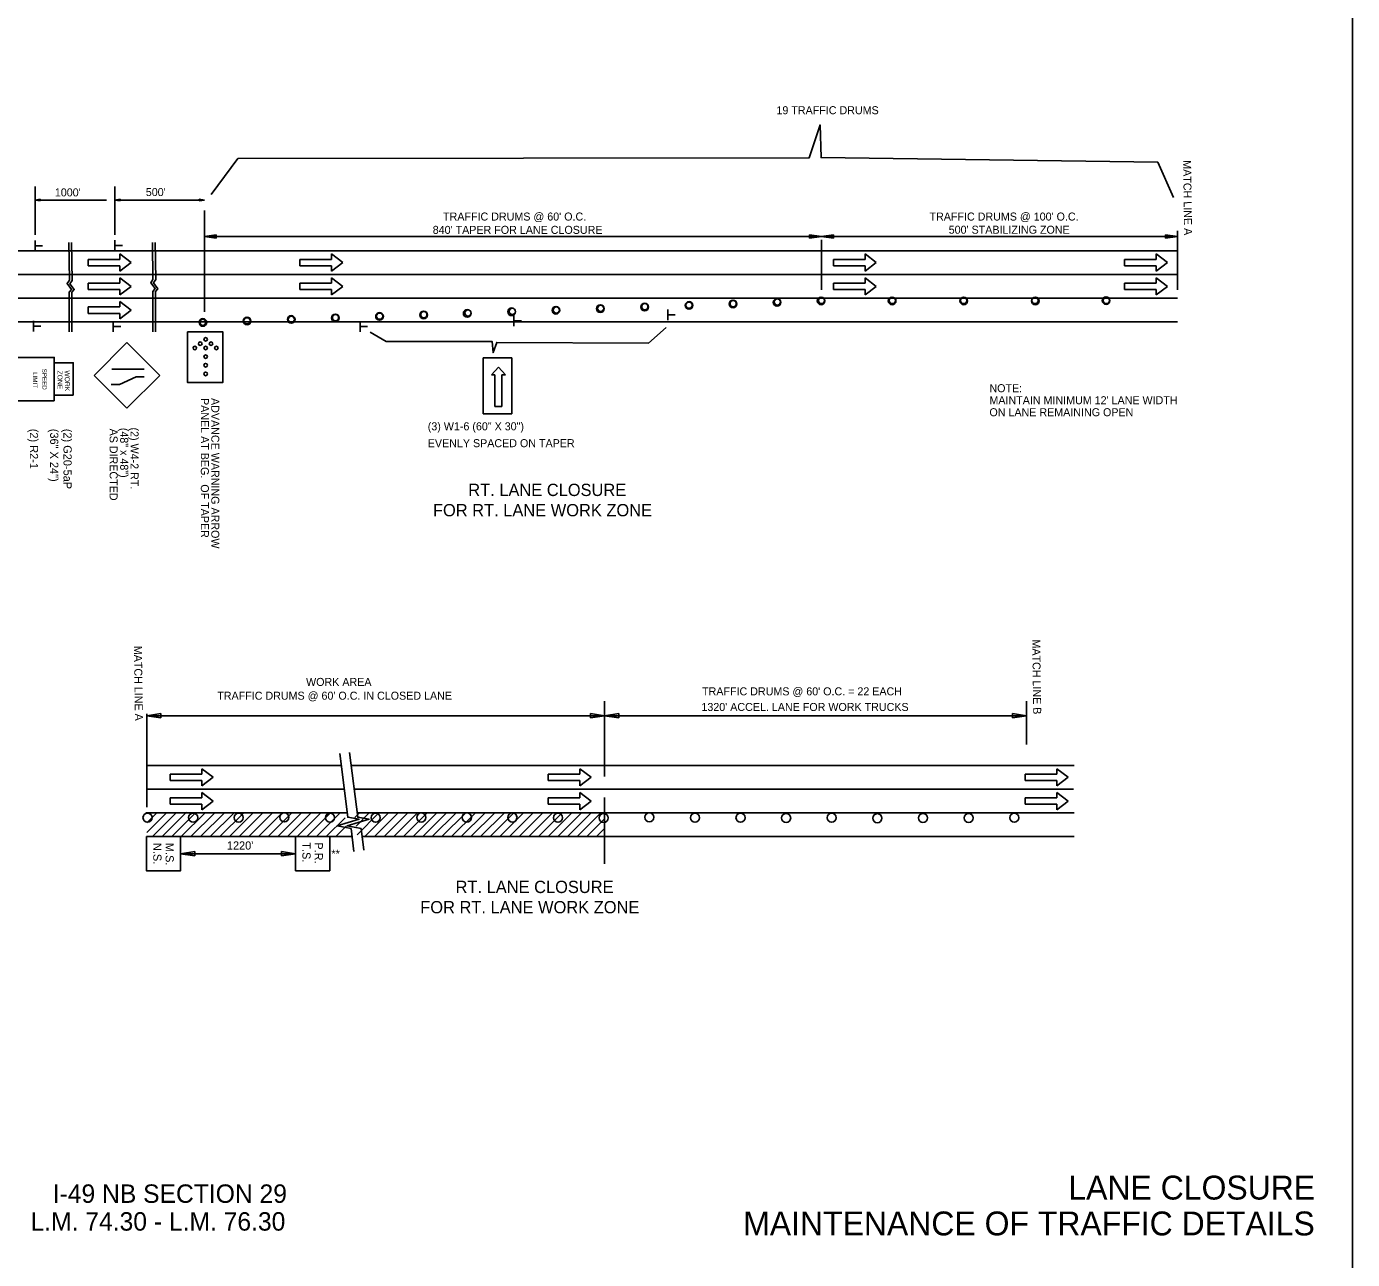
# Model space of a CAD drawing. Extents: x -100 to 745, y -1581 to -107.
# Drawn here: x 248.3 to 345.4, y -368.8 to -278.6 of the extents above; entities that cross this region are included whole.
import ezdxf

# ---------------------------------------------------------------- set-up
doc = ezdxf.new("R2010")
doc.units = 0
for name, color, linetype in [('Default', 7, 'Continuous'), ('R_Contour Annot', 7, 'Continuous'), ('R_Detour Annot', 7, 'Continuous'), ('R_Draft', 7, 'Continuous'), ('R_MOT', 7, 'Continuous'), ('R_ROW', 7, 'Continuous')]:
    doc.layers.add(name, color=color, linetype=linetype)

msp = doc.modelspace()

# ---------------------------------------------------------------- linework, layer by layer
at = {"layer": 'Default'}
for p, q in [((248.914, -290.299), (248.914, -293.82)), ((254.765, -290.299), (254.765, -293.82)), ((249.289, -291.222), (248.914, -291.278)), ((248.914, -291.278), (254.133, -291.278)), ((249.289, -291.335), (248.914, -291.278)), ((249.289, -291.232), (248.977, -291.278)), ((249.289, -291.325), (248.977, -291.278)), ((249.289, -291.241), (249.041, -291.278)), ((249.289, -291.316), (249.041, -291.278)), ((249.289, -291.25), (249.104, -291.278)), ((249.289, -291.306), (249.104, -291.278)), ((249.289, -291.26), (249.167, -291.278)), ((249.289, -291.297), (249.167, -291.278)), ((249.289, -291.27), (249.23, -291.278)), ((249.289, -291.287), (249.23, -291.278)), ((249.289, -291.335), (249.289, -291.222)), ((255.14, -291.222), (254.765, -291.278)), ((254.765, -291.278), (261.312, -291.278)), ((255.14, -291.335), (254.765, -291.278)), ((255.14, -291.232), (254.828, -291.278)), ((255.14, -291.325), (254.828, -291.278)), ((255.14, -291.241), (254.892, -291.278)), ((255.14, -291.316), (254.892, -291.278)), ((255.14, -291.25), (254.955, -291.278)), ((255.14, -291.306), (254.955, -291.278)), ((255.14, -291.26), (255.018, -291.278)), ((255.14, -291.297), (255.018, -291.278)), ((255.14, -291.27), (255.081, -291.278)), ((255.14, -291.287), (255.081, -291.278)), ((255.14, -291.335), (255.14, -291.222)), ((260.937, -291.222), (261.312, -291.278)), ((260.937, -291.222), (260.937, -291.335)), ((260.937, -291.232), (261.25, -291.278)), ((260.937, -291.241), (261.185, -291.278)), ((260.937, -291.25), (261.123, -291.278)), ((260.937, -291.26), (261.059, -291.278)), ((260.937, -291.27), (260.997, -291.278)), ((260.937, -291.335), (261.312, -291.278)), ((260.937, -291.297), (261.059, -291.278)), ((260.937, -291.316), (261.185, -291.278)), ((260.937, -291.325), (261.25, -291.278)), ((260.937, -291.306), (261.123, -291.278)), ((260.937, -291.287), (260.997, -291.278)), ((261.312, -292.038), (261.312, -299.452)), ((248.914, -295.015), (248.914, -294.233)), ((254.765, -294.994), (254.765, -294.212)), ((261.312, -293.95), (262.182, -293.82)), ((306.513, -293.95), (261.312, -293.95)), ((262.182, -294.08), (261.312, -293.95)), ((262.182, -293.82), (262.182, -294.08)), ((305.644, -294.08), (305.644, -293.82)), ((305.644, -293.82), (306.513, -293.95)), ((306.513, -293.95), (305.644, -294.08)), ((306.513, -293.95), (307.383, -293.82)), ((332.591, -293.95), (306.513, -293.95)), ((307.383, -294.08), (306.513, -293.95)), ((306.513, -294.184), (306.513, -297.841)), ((307.383, -293.82), (307.383, -294.08)), ((331.722, -294.08), (331.722, -293.82)), ((331.722, -293.82), (332.591, -293.95)), ((332.591, -293.95), (331.722, -294.08)), ((332.591, -293.536), (332.591, -297.841)), ((245.32, -294.99), (261.312, -294.99)), ((248.925, -294.626), (249.459, -294.626)), ((254.777, -294.605), (255.311, -294.605)), ((255.132, -295.227), (255.132, -295.622)), ((255.132, -295.227), (255.953, -295.859)), ((261.312, -294.32), (261.312, -297.841)), ((261.312, -294.99), (332.591, -294.99)), ((270.63, -295.227), (270.63, -295.622)), ((270.63, -295.227), (271.451, -295.859)), ((309.709, -295.227), (309.709, -295.622)), ((309.709, -295.227), (310.53, -295.859)), ((331.029, -295.227), (331.029, -295.622)), ((331.029, -295.227), (331.849, -295.859)), ((255.132, -295.622), (252.807, -295.622)), ((252.807, -295.622), (252.807, -296.097)), ((255.132, -296.097), (252.807, -296.097)), ((255.953, -295.859), (255.132, -296.492)), ((255.132, -296.097), (255.132, -296.492)), ((270.63, -295.622), (268.304, -295.622)), ((268.304, -295.622), (268.304, -296.097)), ((270.63, -296.097), (268.304, -296.097)), ((271.451, -295.859), (270.63, -296.492)), ((270.63, -296.097), (270.63, -296.492)), ((309.709, -295.622), (307.384, -295.622)), ((307.384, -295.622), (307.384, -296.097)), ((309.709, -296.097), (307.384, -296.097)), ((310.53, -295.859), (309.709, -296.492)), ((309.709, -296.097), (309.709, -296.492)), ((331.029, -295.622), (328.703, -295.622)), ((328.703, -295.622), (328.703, -296.097)), ((331.029, -296.097), (328.703, -296.097)), ((331.849, -295.859), (331.029, -296.492)), ((331.029, -296.097), (331.029, -296.492)), ((245.32, -296.729), (261.312, -296.729)), ((255.132, -296.966), (255.132, -297.361)), ((255.132, -296.966), (255.953, -297.598)), ((261.312, -296.729), (332.591, -296.729)), ((270.63, -296.966), (270.63, -297.361)), ((270.63, -296.966), (271.451, -297.598)), ((309.709, -296.966), (309.709, -297.361)), ((309.709, -296.966), (310.53, -297.598)), ((331.029, -296.966), (331.029, -297.361)), ((331.029, -296.966), (331.849, -297.598)), ((255.132, -297.361), (252.807, -297.361)), ((252.807, -297.361), (252.807, -297.835)), ((255.132, -297.835), (252.807, -297.835)), ((255.953, -297.598), (255.132, -298.23)), ((255.132, -297.835), (255.132, -298.23)), ((270.63, -297.361), (268.304, -297.361)), ((268.304, -297.361), (268.304, -297.835)), ((270.63, -297.835), (268.304, -297.835)), ((271.451, -297.598), (270.63, -298.23)), ((270.63, -297.835), (270.63, -298.23)), ((309.709, -297.361), (307.384, -297.361)), ((307.384, -297.361), (307.384, -297.835)), ((309.709, -297.835), (307.384, -297.835)), ((310.53, -297.598), (309.709, -298.23)), ((309.709, -297.835), (309.709, -298.23)), ((331.029, -297.361), (328.703, -297.361)), ((328.703, -297.361), (328.703, -297.835)), ((331.029, -297.835), (328.703, -297.835)), ((331.849, -297.598), (331.029, -298.23)), ((331.029, -297.835), (331.029, -298.23)), ((245.32, -298.467), (261.312, -298.467)), ((255.132, -299.099), (252.807, -299.099)), ((252.807, -299.099), (252.807, -299.574)), ((255.132, -298.704), (255.132, -299.099)), ((255.132, -298.704), (255.953, -299.336)), ((261.312, -298.467), (332.591, -298.467)), ((255.132, -299.574), (252.807, -299.574)), ((255.953, -299.336), (255.132, -299.969)), ((255.132, -299.574), (255.132, -299.969)), ((283.986, -300.501), (283.986, -299.719)), ((295.257, -300.075), (295.257, -299.293)), ((295.268, -299.686), (295.802, -299.686)), ((245.32, -300.206), (261.312, -300.206)), ((248.788, -300.903), (248.788, -300.12)), ((248.799, -300.514), (249.333, -300.514)), ((254.639, -300.924), (254.639, -300.141)), ((254.65, -300.535), (255.184, -300.535)), ((261.312, -300.206), (332.591, -300.206)), ((272.715, -300.928), (272.715, -300.146)), ((272.727, -300.539), (273.261, -300.539)), ((283.997, -300.112), (284.532, -300.112)), ((255.646, -301.709), (253.237, -304.119)), ((255.646, -301.709), (258.056, -304.119)), ((254.53, -303.655), (256.9, -303.655)), ((282.333, -304.076), (282.851, -303.507)), ((282.851, -303.507), (283.371, -304.076)), ((253.237, -304.119), (255.646, -306.528)), ((254.479, -304.779), (255.092, -304.779)), ((255.092, -304.779), (256.317, -304.217)), ((258.056, -304.119), (255.646, -306.528)), ((256.317, -304.217), (256.9, -304.217)), ((282.592, -304.076), (282.333, -304.076)), ((282.592, -306.406), (282.592, -304.076)), ((283.111, -306.406), (283.111, -304.076)), ((283.111, -304.076), (283.371, -304.076)), ((282.592, -306.406), (283.111, -306.406)), ((290.63, -327.957), (290.63, -333.492)), ((321.54, -327.957), (321.54, -331.149)), ((257.095, -329.036), (258.125, -328.881)), ((257.095, -328.889), (257.095, -333.992)), ((290.63, -329.036), (257.095, -329.036)), ((258.125, -329.19), (257.095, -329.036)), ((258.125, -328.881), (258.125, -329.19)), ((289.6, -329.19), (289.6, -328.882)), ((289.6, -328.882), (290.63, -329.036)), ((290.63, -329.036), (289.6, -329.19)), ((290.63, -329.036), (291.66, -328.881)), ((321.54, -329.036), (290.63, -329.036)), ((291.66, -329.19), (290.63, -329.036)), ((291.66, -328.881), (291.66, -329.19)), ((320.51, -329.19), (320.51, -328.881)), ((320.51, -328.881), (321.54, -329.036)), ((321.54, -329.036), (320.51, -329.19)), ((257.095, -329.695), (257.095, -335.73)), ((257.095, -330.627), (257.095, -335.73)), ((257.095, -330.627), (257.095, -335.73)), ((257.095, -332.673), (271.346, -332.673)), ((261.133, -332.91), (261.133, -333.305)), ((261.133, -332.91), (261.954, -333.543)), ((272.074, -332.673), (290.63, -332.673)), ((288.812, -332.91), (288.812, -333.305)), ((288.812, -332.91), (289.632, -333.543)), ((290.63, -332.673), (325.019, -332.673)), ((323.754, -332.91), (323.754, -333.305)), ((323.754, -332.91), (324.575, -333.543)), ((261.133, -333.305), (258.808, -333.305)), ((258.808, -333.305), (258.808, -333.78)), ((261.133, -333.78), (258.808, -333.78)), ((261.954, -333.543), (261.133, -334.175)), ((261.133, -333.78), (261.133, -334.175)), ((288.812, -333.305), (286.486, -333.305)), ((286.486, -333.305), (286.486, -333.78)), ((288.812, -333.78), (286.486, -333.78)), ((289.632, -333.543), (288.812, -334.175)), ((288.812, -333.78), (288.812, -334.175)), ((323.754, -333.305), (321.429, -333.305)), ((321.429, -333.305), (321.429, -333.78)), ((323.754, -333.78), (321.429, -333.78)), ((324.575, -333.543), (323.754, -334.175)), ((323.754, -333.78), (323.754, -334.175)), ((257.095, -334.411), (271.563, -334.411)), ((261.133, -335.044), (258.808, -335.044)), ((258.808, -335.044), (258.808, -335.518)), ((261.133, -334.649), (261.133, -335.044)), ((261.133, -334.649), (261.954, -335.281)), ((272.291, -334.411), (290.581, -334.411)), ((288.812, -335.044), (286.486, -335.044)), ((286.486, -335.044), (286.486, -335.518)), ((288.812, -334.649), (288.812, -335.044)), ((288.812, -334.649), (289.632, -335.281)), ((290.581, -334.411), (324.97, -334.411)), ((323.754, -335.044), (321.429, -335.044)), ((321.429, -335.044), (321.429, -335.518)), ((323.754, -334.649), (323.754, -335.044)), ((323.754, -334.649), (324.575, -335.281)), ((261.133, -335.518), (258.808, -335.518)), ((261.954, -335.281), (261.133, -335.913)), ((261.133, -335.518), (261.133, -335.913)), ((288.812, -335.518), (286.486, -335.518)), ((289.632, -335.281), (288.812, -335.913)), ((288.812, -335.518), (288.812, -335.913)), ((323.754, -335.518), (321.429, -335.518)), ((324.575, -335.281), (323.754, -335.913)), ((323.754, -335.518), (323.754, -335.913)), ((257.025, -336.15), (271.718, -336.15)), ((257.096, -337.589), (258.535, -336.15)), ((257.096, -336.882), (257.828, -336.15)), ((257.504, -337.888), (259.242, -336.15)), ((258.211, -337.888), (260.004, -336.094)), ((258.918, -337.888), (260.656, -336.15)), ((259.625, -337.888), (261.363, -336.15)), ((260.332, -337.888), (262.07, -336.15)), ((261.039, -337.888), (262.777, -336.15)), ((261.746, -337.888), (263.485, -336.15)), ((262.453, -337.888), (264.192, -336.15)), ((263.16, -337.888), (264.899, -336.15)), ((263.868, -337.888), (265.606, -336.15)), ((264.575, -337.888), (266.313, -336.15)), ((265.282, -337.888), (267.02, -336.15)), ((265.989, -337.888), (267.727, -336.15)), ((266.696, -337.888), (268.434, -336.15)), ((267.403, -337.888), (269.141, -336.15)), ((268.11, -337.888), (269.849, -336.15)), ((268.817, -337.888), (270.556, -336.15)), ((269.524, -337.888), (271.263, -336.15)), ((270.232, -337.888), (271.62, -336.5)), ((272.346, -336.481), (272.677, -336.15)), ((272.422, -337.112), (273.384, -336.15)), ((272.498, -337.743), (274.091, -336.15)), ((272.508, -336.15), (290.63, -336.15)), ((273.06, -337.888), (274.798, -336.15)), ((273.767, -337.888), (275.505, -336.15)), ((274.474, -337.888), (276.212, -336.15)), ((275.181, -337.888), (276.92, -336.15)), ((275.888, -337.888), (277.627, -336.15)), ((276.596, -337.888), (278.334, -336.15)), ((277.303, -337.888), (279.041, -336.15)), ((278.01, -337.888), (279.748, -336.15)), ((278.717, -337.888), (280.455, -336.15)), ((279.424, -337.888), (281.162, -336.15)), ((280.131, -337.888), (281.869, -336.15)), ((280.838, -337.888), (282.576, -336.15)), ((281.545, -337.888), (283.284, -336.15)), ((282.252, -337.888), (283.991, -336.15)), ((282.959, -337.888), (284.698, -336.15)), ((283.667, -337.888), (285.405, -336.15)), ((284.374, -337.888), (286.112, -336.15)), ((285.081, -337.888), (286.819, -336.15)), ((285.788, -337.888), (287.526, -336.15)), ((286.495, -337.888), (288.233, -336.15)), ((287.202, -337.888), (288.94, -336.15)), ((287.909, -337.888), (289.647, -336.15)), ((288.616, -337.888), (290.355, -336.15)), ((289.323, -337.888), (290.63, -336.581)), ((290.63, -336.15), (325.019, -336.15)), ((257.073, -337.888), (272.134, -337.888)), ((270.939, -337.888), (271.696, -337.131)), ((272.899, -337.888), (290.63, -337.888)), ((290.031, -337.888), (290.63, -337.288)), ((290.63, -337.888), (325.019, -337.888)), ((259.573, -339.138), (260.604, -338.984)), ((267.994, -339.138), (259.573, -339.138)), ((260.604, -339.293), (259.573, -339.138)), ((260.604, -338.984), (260.604, -339.293)), ((266.964, -339.293), (266.964, -338.984)), ((266.964, -338.984), (267.994, -339.138)), ((267.994, -339.138), (266.964, -339.293))]:
    msp.add_line(p, q, dxfattribs=at)
for points in [[(261.799, -290.865), (263.774, -288.247), (305.6, -288.199), (306.406, -285.78), (306.479, -288.165), (331.147, -288.498), (332.289, -291.096)], [(251.381, -294.379), (251.423, -297.152), (251.26, -297.394), (251.577, -297.827), (251.41, -298.027), (251.41, -300.917)], [(251.58, -294.379), (251.623, -297.161), (251.46, -297.402), (251.777, -297.835), (251.61, -298.035), (251.61, -300.917)], [(257.506, -294.379), (257.548, -297.089), (257.385, -297.331), (257.702, -297.764), (257.535, -297.964), (257.534, -300.917)], [(257.706, -294.379), (257.747, -297.098), (257.585, -297.339), (257.901, -297.772), (257.735, -297.972), (257.734, -300.917)], [(273.468, -300.949), (274.626, -301.63), (282.391, -301.63), (282.459, -302.448), (282.731, -301.698), (293.835, -301.767), (295.129, -300.608)], [(271.238, -331.809), (271.819, -336.465), (272.645, -336.611), (271.042, -337.097), (272.062, -337.291), (272.265, -338.976)], [(271.955, -331.719), (272.548, -336.465), (273.373, -336.611), (271.771, -337.097), (272.791, -337.291), (272.981, -338.872)]]:
    msp.add_lwpolyline(points, dxfattribs=at)
for points in [[(260.087, -300.92), (260.087, -304.644), (262.663, -304.644), (262.663, -300.92)], [(250.32, -305.968), (246.908, -305.968), (246.908, -302.797), (250.32, -302.797)], [(281.738, -302.841), (281.738, -306.927), (283.828, -306.927), (283.828, -302.841)], [(251.707, -305.572), (250.32, -305.572), (250.32, -303.194), (251.707, -303.194)], [(257.073, -337.888), (259.573, -337.888), (259.573, -340.388), (257.073, -340.388)], [(267.994, -337.888), (270.494, -337.888), (270.494, -340.388), (267.994, -340.388)]]:
    msp.add_lwpolyline(points, close=True, dxfattribs=at)
for centre, radius in [((287.064, -299.345), 0.281), ((287.1, -299.321), 0.229), ((290.314, -299.229), 0.281), ((290.336, -299.206), 0.229), ((293.564, -299.113), 0.281), ((293.573, -299.091), 0.229), ((296.814, -298.996), 0.281), ((296.81, -298.977), 0.229), ((300.035, -298.886), 0.281), ((300.047, -298.862), 0.229), ((303.26, -298.775), 0.281), ((303.284, -298.747), 0.229), ((306.485, -298.664), 0.281), ((306.508, -298.632), 0.229), ((306.52, -298.633), 0.229), ((311.69, -298.664), 0.281), ((311.697, -298.634), 0.229), ((316.932, -298.664), 0.281), ((316.924, -298.634), 0.229), ((322.174, -298.664), 0.281), ((322.151, -298.634), 0.229), ((327.361, -298.638), 0.281), ((327.378, -298.634), 0.229), ((261.207, -300.242), 0.281), ((261.193, -300.237), 0.229), ((261.205, -300.238), 0.229), ((264.44, -300.131), 0.281), ((264.442, -300.124), 0.229), ((267.674, -300.021), 0.281), ((267.679, -300.009), 0.229), ((270.907, -299.91), 0.281), ((270.916, -299.894), 0.229), ((274.141, -299.799), 0.281), ((274.152, -299.779), 0.229), ((277.374, -299.688), 0.281), ((277.389, -299.665), 0.229), ((280.563, -299.578), 0.281), ((280.626, -299.55), 0.229), ((283.814, -299.462), 0.281), ((283.863, -299.435), 0.229), ((260.615, -302.11), 0.131), ((261.01, -301.794), 0.131), ((261.404, -301.478), 0.131), ((261.404, -302.11), 0.131), ((261.799, -301.794), 0.131), ((262.194, -302.11), 0.131), ((261.404, -302.743), 0.131), ((261.404, -303.375), 0.131), ((261.404, -304.007), 0.131), ((257.15, -336.492), 0.333), ((260.491, -336.492), 0.333), ((263.832, -336.491), 0.333), ((267.174, -336.471), 0.333), ((270.515, -336.492), 0.333), ((273.856, -336.503), 0.333), ((277.197, -336.487), 0.333), ((280.538, -336.487), 0.333), ((283.879, -336.487), 0.333), ((287.22, -336.503), 0.333), ((290.561, -336.515), 0.333), ((293.902, -336.467), 0.333), ((297.243, -336.499), 0.333), ((300.584, -336.499), 0.333), ((303.925, -336.515), 0.333), ((307.266, -336.502), 0.333), ((310.607, -336.537), 0.333), ((313.948, -336.515), 0.333), ((317.289, -336.518), 0.333), ((320.63, -336.502), 0.333)]:
    msp.add_circle(centre, radius, dxfattribs=at)
at = {"layer": 'R_Contour Annot'}
msp.add_lwpolyline([(175.406, -260.582), (345.406, -260.582), (345.406, -370.582), (175.406, -370.582)], close=True, dxfattribs=at)
at = {"layer": 'R_Detour Annot'}
msp.add_line((290.63, -339.884), (290.63, -335.022), dxfattribs=at)
at = {"layer": 'R_Draft'}
msp.add_lwpolyline([(175.406, -260.582), (175.406, -370.582), (345.406, -370.582), (345.406, -260.582)], close=True, dxfattribs=at)

# ---------------------------------------------------------------- texts
at = {"layer": 'Default'}
for s, height, p in [('19 TRAFFIC DRUMS', 0.5862, (303.215, -284.995)), ("1000'", 0.5862, (250.362, -291.011)), ("500'", 0.5862, (257.023, -290.986)), ("TRAFFIC DRUMS @ 60' O.C.", 0.5862, (278.796, -292.78)), ("TRAFFIC DRUMS @ 100' O.C.", 0.5862, (314.427, -292.78)), ("840' TAPER FOR LANE CLOSURE", 0.5862, (278.04, -293.754)), ("500' STABILIZING ZONE", 0.5862, (315.832, -293.744)), ('NOTE:', 0.5862, (318.815, -305.348)), ("MAINTAIN MINIMUM 12' LANE WIDTH", 0.5862, (318.815, -306.228)), ('ON LANE REMAINING OPEN', 0.5862, (318.815, -307.107)), ('WORK AREA', 0.5862, (268.762, -326.853)), ("TRAFFIC DRUMS @ 60' O.C. IN CLOSED LANE", 0.5862, (262.258, -327.861)), ("TRAFFIC DRUMS @ 60' O.C. = 22 EACH", 0.5862, (297.767, -327.542)), ("1320' ACCEL. LANE FOR WORK TRUCKS", 0.5862, (297.719, -328.685)), ("1220'", 0.6, (262.962, -338.835)), ('**', 0.6, (270.617, -339.438)), ('I-49 NB SECTION 29', 1.35, (250.207, -364.699)), ('L.M. 74.30 - L.M. 76.30', 1.35, (248.58, -366.732))]:
    msp.add_text(s, height=height, dxfattribs=at).set_placement(p)
for s, height, rotation, p in [('MATCH LINE A', 0.5862, 270.80593, (332.997, -288.369)), ('LIMIT', 0.3303, 270, (248.759, -303.876)), ('SPEED', 0.3303, 270, (249.441, -303.622)), ('ZONE', 0.3544, 270.10045, (250.561, -303.767)), ('WORK', 0.3544, 270.10045, (251.092, -303.752)), ('PANEL AT BEG.  OF TAPER', 0.5862, 270, (261.055, -305.774)), ('ADVANCE WARNING ARROW', 0.5862, 270, (261.819, -305.774)), ('(3) W1-6 (60" X 30")', 0.5862, 0.00754, (277.676, -308.138)), ('(2) R2-1', 0.6, 270, (248.533, -308.026)), ('(36" X 24")', 0.6, 270, (250.017, -308.026)), ('(2) G20-5aP', 0.6, 270, (250.995, -308.026)), ('AS DIRECTED', 0.5862, 270, (254.374, -308.013)), ('(48" x 48")', 0.5862, 270, (255.146, -307.956)), ('(2) W4-2 RT.', 0.5862, 270, (255.904, -307.932)), ('EVENLY SPACED ON TAPER', 0.5862, 0.00754, (277.676, -309.373)), ('MATCH LINE A', 0.5862, 270.80593, (256.152, -323.917)), ('MATCH LINE B', 0.5862, 270.80593, (321.947, -323.454)), ('N.S.', 0.6, 270, (257.573, -338.347)), ('M.S.', 0.6, 270, (258.473, -338.347)), ('T.S.', 0.6, 270, (268.494, -338.3)), ('P.R.', 0.6, 270, (269.394, -338.3))]:
    msp.add_text(s, height=height, rotation=rotation, dxfattribs=at).set_placement(p)
at = {"layer": 'R_MOT'}
for s, p in [('LANE CLOSURE', (324.596, -364.457)), ('MAINTENANCE OF TRAFFIC DETAILS', (300.779, -367.082))]:
    msp.add_text(s, height=1.75, dxfattribs=at).set_placement(p)
at = {"layer": 'R_ROW'}
for s, p in [('RT. LANE CLOSURE ', (280.643, -312.949)), ('FOR RT. LANE WORK ZONE', (278.056, -314.434)), ('RT. LANE CLOSURE ', (279.714, -342.016)), ('FOR RT. LANE WORK ZONE', (277.127, -343.501))]:
    msp.add_text(s, height=0.9, dxfattribs=at).set_placement(p)

doc.saveas('drawing.dxf')
